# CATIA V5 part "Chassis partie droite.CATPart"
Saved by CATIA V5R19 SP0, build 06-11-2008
Part number: Bati.1
Bounding box of the stored display mesh (mm): x 0 to 60, y 0 to 700, z 0 to 900
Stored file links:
  C:\Users\Hicham57\Desktop\Chassis presse\Chassis partie droite.CATPart
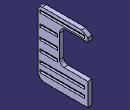
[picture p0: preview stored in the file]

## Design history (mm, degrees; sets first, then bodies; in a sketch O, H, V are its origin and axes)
Body1 (main body)
  Sketch1 on yz-plane, origin (0, 0, 0), H (0, 1, 0), V (0, 0, 1)
    line L1 (101.0295, 0) -> (700, 0)
    point P1 (700, 0)
    line L2 (700, 0) -> (700, 320)
    line L3 (700, 320) -> (365.2402, 320)
    line L4 (300, 385.2402) -> (300, 701.3231)
    line L5 (393.6769, 795) -> (700, 795)
    point P3 (700, 795)
    line L6 (700, 795) -> (700, 850)
    line L7 (700, 850) -> (613.3975, 900)
    line L8 (613.3975, 900) -> (58.246, 900)
    point P6 (0, 900)
    line L9 (0, 841.754) -> (0, 101.0295)
    arc A1 centre (365.2402, 385.2402) radius 65.2402 from (365.2402, 320) to (300, 385.2402) cw
    arc A2 centre (393.6769, 701.3231) radius 93.6769 from (300, 701.3231) to (393.6769, 795) cw
    arc A3 centre (58.246, 841.754) radius 58.246 from (58.246, 900) to (0, 841.754) ccw
    arc A4 centre (101.0295, 101.0295) radius 101.0295 from (101.0295, 0) to (0, 101.0295) cw
    length L2 = 320
    distance L3 L5 = 475
    distance L4 L9 = 300
    length L7 = 100
    angle L5 L7 = 150
    radius A1 = 65.2402
    radius A2 = 93.6769
    distance P6 O = 900
    radius A3 = 58.246
    distance O P1 = 700
    radius A4 = 101.0295
    horizontal: L1 H, L3 H, L5 H, L8 H
    vertical: L2 V, L4 V, L6 V, L9 V
    coincidence: P3 L2, P6 V, L8 P6, L9 P6, L1 O, L9 O
    tangency: A1 L3, A1 L4, A2 L4, A2 L5, A3 L8, A3 L9, A4 L1, A4 L9
  Pad1: profile Sketch1, direction (1, 0, 0), length 60
  Sketch2 on end face of Pad1, origin (60, 0, 0), H (0, 1, 0), V (0, 0, 1)
  Sketch3 on start face of Pad1, origin (0, 0, 0), H (0, -1, 0), V (0, 0, 1)
    line L1 (-655, 855) -> (-25, 855)
    line L2 (-25, 855) -> (-25, 815)
    line L3 (-25, 815) -> (-655, 815)
    line L4 (-655, 815) -> (-655, 855)
    line L5 (-275, 685) -> (-25, 685)
    line L6 (-25, 685) -> (-25, 645)
    line L7 (-25, 645) -> (-275, 645)
    line L8 (-275, 645) -> (-275, 685)
    point P7 (-25, 645)
    point P9 (-275, 525)
    line L9 (-275, 525) -> (-25, 525)
    line L10 (-25, 525) -> (-25, 485)
    line L11 (-25, 485) -> (-275, 485)
    line L12 (-275, 485) -> (-275, 525)
    point P11 (-25, 485)
    line L13 (-275, 380) -> (-25, 380)
    line L14 (-25, 380) -> (-25, 340)
    line L15 (-25, 340) -> (-275, 340)
    line L16 (-275, 340) -> (-275, 380)
    point P17 (-655, 240)
    line L17 (-655, 240) -> (-25, 240)
    line L18 (-25, 240) -> (-25, 200)
    line L19 (-25, 200) -> (-655, 200)
    line L20 (-655, 200) -> (-655, 240)
    point P19 (-25, 200)
    point P21 (-655, 130)
    line L21 (-655, 130) -> (-25, 130)
    line L22 (-25, 130) -> (-25, 90)
    line L23 (-25, 90) -> (-655, 90)
    line L24 (-655, 90) -> (-655, 130)
    point P23 (-25, 90)
    length L1 = 630
    length L2 = 40
    distance L3 H = 815
    length L8 = 40
    distance L11 L9 = 40
    distance L15 L13 = 40
    distance L6 L8 = 250
    length L15 = 250
    distance V L6 = 25
    distance L7 H = 645
    distance L11 H = 485
    distance L14 V = 25
    distance L15 H = 340
    distance L19 H = 200
    length L20 = 40
    length L24 = 40
    distance H L23 = 90
    horizontal: L1 H, L3 H, L5 H, L7 H, L9 H, L11 H, L13 H, L15 H, L17 H, L19 H, L21 H, L23 H
    vertical: L2 V, L4 V, L6 V, L8 V, L10 V, L12 V, L14 V, L16 V, L18 V, L20 V, L22 V, L24 V
    coincidence: P7 L2, P9 L8, P11 L2, P17 L4, P19 L14, P21 L4, P23 L2
  Pocket1: profile Sketch3, direction (1, 0, 0), length 25
  Sketch4 on end face of Pad1, origin (60, 0, 0), H (0, 1, 0), V (0, 0, 1)
    circle A1 centre (165, 835) radius 10
    point P1 (165, 835)
    circle A2 centre (565, 835) radius 10
    point P2 (565, 835)
    circle A3 centre (80, 665) radius 10
    point P3 (80, 665)
    circle A4 centre (220, 665) radius 10
    point P4 (220, 665)
    circle A5 centre (80, 505) radius 10
    point P5 (80, 505)
    circle A6 centre (220, 505) radius 10
    point P6 (220, 505)
    circle A7 centre (80, 360) radius 10
    point P7 (80, 360)
    circle A8 centre (220, 360) radius 10
    point P8 (220, 360)
    circle A9 centre (165, 220) radius 10
    point P9 (165, 220)
    circle A10 centre (365, 220) radius 10
    point P10 (365, 220)
    circle A11 centre (565, 220) radius 10
    point P11 (565, 220)
    circle A12 centre (165, 110) radius 10
    point P12 (165, 110)
    circle A13 centre (365, 110) radius 10
    point P13 (365, 110)
    circle A14 centre (565, 110) radius 10
    point P14 (565, 110)
    circle A15 centre (365, 835) radius 10
    point P15 (365, 835)
    reference projected line E1 (25, 815) -> (25, 855) from edge [end face of Pocket1 | face of Pocket1 from Sketch3.L2]
    reference projected line E2 (655, 815) -> (25, 815) from edge [end face of Pocket1 | face of Pocket1 from Sketch3.L3]
    reference projected line E3 (655, 815) -> (25, 815) from edge [end face of Pocket1 | face of Pocket1 from Sketch3.L3]
    reference projected line E4 (655, 815) -> (25, 815) from edge [end face of Pocket1 | face of Pocket1 from Sketch3.L3]
    reference projected line E5 (25, 200) -> (25, 240) from edge [start face of Pad1 | face of Pocket1 from Sketch3.L18]
    reference projected line E6 (655, 200) -> (25, 200) from edge [end face of Pocket1 | face of Pocket1 from Sketch3.L19]
    reference projected line E7 (655, 200) -> (25, 200) from edge [end face of Pocket1 | face of Pocket1 from Sketch3.L19]
    reference projected line E8 (655, 200) -> (25, 200) from edge [end face of Pocket1 | face of Pocket1 from Sketch3.L19]
    reference projected line E9 (25, 90) -> (25, 130) from edge [end face of Pocket1 | face of Pocket1 from Sketch3.L22]
    reference projected line E10 (655, 90) -> (25, 90) from edge [end face of Pocket1 | face of Pocket1 from Sketch3.L23]
    reference projected line E11 (655, 90) -> (25, 90) from edge [end face of Pocket1 | face of Pocket1 from Sketch3.L23]
    reference projected line E12 (655, 90) -> (25, 90) from edge [end face of Pocket1 | face of Pocket1 from Sketch3.L23]
    reference projected line E13 (25, 645) -> (25, 685) from edge [end face of Pocket1 | face of Pocket1 from Sketch3.L6]
    reference projected line E14 (275, 685) -> (275, 645) from edge [end face of Pocket1 | face of Pocket1 from Sketch3.L8]
    reference projected line E15 (275, 645) -> (25, 645) from edge [end face of Pocket1 | face of Pocket1 from Sketch3.L7]
    reference projected line E16 (25, 485) -> (25, 525) from edge [end face of Pocket1 | face of Pocket1 from Sketch3.L10]
    reference projected line E17 (275, 525) -> (275, 485) from edge [end face of Pocket1 | face of Pocket1 from Sketch3.L12]
    reference projected line E18 (275, 485) -> (25, 485) from edge [end face of Pocket1 | face of Pocket1 from Sketch3.L11]
    reference projected line E19 (25, 340) -> (25, 380) from edge [start face of Pad1 | face of Pocket1 from Sketch3.L14]
    reference projected line E20 (275, 380) -> (275, 340) from edge [end face of Pocket1 | face of Pocket1 from Sketch3.L16]
    reference projected line E21 (275, 340) -> (25, 340) from edge [end face of Pocket1 | face of Pocket1 from Sketch3.L15]
    radius A1 = 10
    radius A15 = 10
    radius A2 = 10
    radius A3 = 10
    radius A4 = 10
    radius A5 = 10
    radius A6 = 10
    radius A7 = 10
    radius A8 = 10
    radius A9 = 10
    radius A10 = 10
    radius A11 = 10
    radius A12 = 10
    radius A13 = 10
    radius A14 = 10
    distance A1 E1 = 150
    distance A1 E2 = 10
    distance A15 E3 = 10
    distance A2 E4 = 10
    distance P15 P1 = 200
    distance P2 P15 = 200
    distance P9 E5 = 140
    distance P9 P10 = 200
    distance P11 P10 = 200
    distance P9 E6 = 20
    distance P10 E7 = 20
    distance P11 E8 = 20
    distance P12 E9 = 140
    distance P12 P13 = 200
    distance P14 P13 = 200
    distance A12 E10 = 10
    distance A13 E11 = 10
    distance A14 E12 = 10
    distance P3 P4 = 140
    distance P3 E13 = 55
    distance P4 E14 = 55
    distance A3 E15 = 10
    distance E16 P5 = 55
    distance P5 P6 = 140
    distance P6 E17 = 55
    distance P6 E18 = 20
    distance P7 E19 = 55
    distance P8 P7 = 140
    distance E20 P8 = 55
    distance P8 E21 = 20
  Pocket2: profile Sketch4, direction (-1, 0, 0), length 60
  Sketch5 on end face of Pad1, origin (60, 0, 0), H (0, 1, 0), V (0, 0, 1)
    line L1 (25, 815) -> (655, 815)
    line L2 (655, 815) -> (655, 855)
    line L3 (655, 855) -> (25, 855)
    line L4 (25, 855) -> (25, 815)
    line L5 (25, 645) -> (275, 645)
    line L6 (275, 645) -> (275, 685)
    line L7 (275, 685) -> (25, 685)
    line L8 (25, 685) -> (25, 645)
    line L9 (25, 485) -> (275, 485)
    line L10 (275, 485) -> (275, 525)
    line L11 (275, 525) -> (25, 525)
    line L12 (25, 525) -> (25, 485)
    line L13 (25, 340) -> (275, 340)
    line L14 (275, 340) -> (275, 380)
    line L15 (275, 380) -> (25, 380)
    line L16 (25, 380) -> (25, 340)
    line L17 (25, 200) -> (655, 200)
    line L18 (655, 200) -> (655, 240)
    line L19 (655, 240) -> (25, 240)
    line L20 (25, 240) -> (25, 200)
    line L21 (25, 90) -> (655, 90)
    line L22 (655, 90) -> (655, 130)
    line L23 (655, 130) -> (25, 130)
    line L24 (25, 130) -> (25, 90)
    reference projected line E1 (655, 815) -> (25, 815) from edge [end face of Pocket1 | face of Pocket1 from Sketch3.L3]
    reference projected line E2 (25, 855) -> (655, 855) from edge [end face of Pocket1 | face of Pocket1 from Sketch3.L1]
    reference projected line E3 (655, 855) -> (655, 815) from edge [end face of Pocket1 | face of Pocket1 from Sketch3.L4]
    reference projected line E4 (25, 815) -> (25, 855) from edge [end face of Pocket1 | face of Pocket1 from Sketch3.L2]
    reference projected line E5 (275, 645) -> (25, 645) from edge [end face of Pocket1 | face of Pocket1 from Sketch3.L7]
    reference projected line E6 (25, 685) -> (275, 685) from edge [end face of Pocket1 | face of Pocket1 from Sketch3.L5]
    reference projected line E7 (25, 645) -> (25, 685) from edge [end face of Pocket1 | face of Pocket1 from Sketch3.L6]
    reference projected line E8 (275, 685) -> (275, 645) from edge [end face of Pocket1 | face of Pocket1 from Sketch3.L8]
    reference projected line E9 (25, 525) -> (275, 525) from edge [end face of Pocket1 | face of Pocket1 from Sketch3.L9]
    reference projected line E10 (275, 485) -> (25, 485) from edge [end face of Pocket1 | face of Pocket1 from Sketch3.L11]
    reference projected line E11 (275, 525) -> (275, 485) from edge [end face of Pocket1 | face of Pocket1 from Sketch3.L12]
    reference projected line E12 (25, 485) -> (25, 525) from edge [end face of Pocket1 | face of Pocket1 from Sketch3.L10]
    reference projected line E13 (25, 380) -> (275, 380) from edge [end face of Pocket1 | face of Pocket1 from Sketch3.L13]
    reference projected line E14 (275, 340) -> (25, 340) from edge [end face of Pocket1 | face of Pocket1 from Sketch3.L15]
    reference projected line E15 (275, 380) -> (275, 340) from edge [end face of Pocket1 | face of Pocket1 from Sketch3.L16]
    reference projected line E16 (25, 340) -> (25, 380) from edge [end face of Pocket1 | face of Pocket1 from Sketch3.L14]
    reference projected line E17 (25, 240) -> (655, 240) from edge [end face of Pocket1 | face of Pocket1 from Sketch3.L17]
    reference projected line E18 (655, 240) -> (655, 200) from edge [end face of Pocket1 | face of Pocket1 from Sketch3.L20]
    reference projected line E19 (655, 200) -> (25, 200) from edge [end face of Pocket1 | face of Pocket1 from Sketch3.L19]
    reference projected line E20 (25, 200) -> (25, 240) from edge [end face of Pocket1 | face of Pocket1 from Sketch3.L18]
    reference projected line E21 (25, 130) -> (655, 130) from edge [end face of Pocket1 | face of Pocket1 from Sketch3.L21]
    reference projected line E22 (655, 90) -> (25, 90) from edge [end face of Pocket1 | face of Pocket1 from Sketch3.L23]
    reference projected line E23 (655, 130) -> (655, 90) from edge [end face of Pocket1 | face of Pocket1 from Sketch3.L24]
    reference projected line E24 (25, 90) -> (25, 130) from edge [end face of Pocket1 | face of Pocket1 from Sketch3.L22]
    horizontal: L1 H, L3 H, L5 H, L7 H, L9 H, L11 H, L13 H, L15 H, L17 H, L19 H, L21 H, L23 H
    vertical: L2 V, L4 V, L6 V, L8 V, L10 V, L12 V, L14 V, L16 V, L18 V, L20 V, L22 V, L24 V
    coincidence: L1 E1, L3 E2, L2 E3, L4 E4, L5 E5, L7 E6, L8 E7, L6 E8, L11 E9, L9 E10, E11 L10, L12 E12, L15 E13, L13 E14, L14 E15, E16 L16, L19 E17, L18 E18, L17 E19, L20 E20, L23 E21, L21 E22, L22 E23, L24 E24
  Pocket3: profile Sketch5, direction (-1, 0, 0), length 30
  Sketch6 on start face of Pad1, origin (0, 0, 0), H (0, -1, 0), V (0, 0, 1)
    line L1 (-655, 855) -> (-25, 855)
    line L2 (-25, 855) -> (-25, 815)
    line L3 (-25, 815) -> (-655, 815)
    line L4 (-655, 815) -> (-655, 855)
    line L5 (-275, 685) -> (-25, 685)
    line L6 (-25, 685) -> (-25, 645)
    line L7 (-25, 645) -> (-275, 645)
    line L8 (-275, 645) -> (-275, 685)
    line L9 (-275, 525) -> (-25, 525)
    line L10 (-25, 525) -> (-25, 485)
    line L11 (-25, 485) -> (-275, 485)
    line L12 (-275, 485) -> (-275, 525)
    line L13 (-275, 380) -> (-25, 380)
    line L14 (-25, 380) -> (-25, 340)
    line L15 (-25, 340) -> (-275, 340)
    line L16 (-275, 340) -> (-275, 380)
    point P15 (-25, 340)
    line L17 (-655, 130) -> (-25, 130)
    line L18 (-25, 130) -> (-25, 90)
    line L19 (-25, 90) -> (-655, 90)
    line L20 (-655, 90) -> (-655, 130)
    reference projected line E1 (-25, 855) -> (-655, 855) from edge [start face of Pad1 | face of Pocket1 from Sketch3.L1]
    reference projected line E2 (-655, 815) -> (-25, 815) from edge [start face of Pad1 | face of Pocket1 from Sketch3.L3]
    reference projected line E3 (-25, 815) -> (-25, 855) from edge [start face of Pad1 | face of Pocket1 from Sketch3.L2]
    reference projected line E4 (-655, 855) -> (-655, 815) from edge [start face of Pad1 | face of Pocket1 from Sketch3.L4]
    reference projected line E5 (-25, 685) -> (-275, 685) from edge [start face of Pad1 | face of Pocket1 from Sketch3.L5]
    reference projected line E6 (-25, 645) -> (-25, 685) from edge [start face of Pad1 | face of Pocket1 from Sketch3.L6]
    reference projected line E7 (-275, 645) -> (-25, 645) from edge [start face of Pad1 | face of Pocket1 from Sketch3.L7]
    reference projected line E8 (-275, 685) -> (-275, 645) from edge [start face of Pad1 | face of Pocket1 from Sketch3.L8]
    reference projected line E9 (-25, 525) -> (-275, 525) from edge [start face of Pad1 | face of Pocket1 from Sketch3.L9]
    reference projected line E10 (-275, 485) -> (-25, 485) from edge [start face of Pad1 | face of Pocket1 from Sketch3.L11]
    reference projected line E11 (-275, 525) -> (-275, 485) from edge [start face of Pad1 | face of Pocket1 from Sketch3.L12]
    reference projected line E12 (-25, 485) -> (-25, 525) from edge [start face of Pad1 | face of Pocket1 from Sketch3.L10]
    reference projected line E13 (-25, 380) -> (-275, 380) from edge [start face of Pad1 | face of Pocket1 from Sketch3.L13]
    reference projected line E14 (-275, 340) -> (-25, 340) from edge [start face of Pad1 | face of Pocket1 from Sketch3.L15]
    reference projected line E15 (-275, 380) -> (-275, 340) from edge [start face of Pad1 | face of Pocket1 from Sketch3.L16]
    line L21 (-655, 240) -> (-25, 240)
    line L22 (-25, 240) -> (-25, 200)
    line L23 (-25, 200) -> (-655, 200)
    line L24 (-655, 200) -> (-655, 240)
    reference projected line E16 (-25, 200) -> (-25, 240) from edge [start face of Pad1 | face of Pocket1 from Sketch3.L18]
    reference projected line E17 (-655, 240) -> (-655, 200) from edge [start face of Pad1 | face of Pocket1 from Sketch3.L20]
    reference projected line E18 (-655, 200) -> (-25, 200) from edge [start face of Pad1 | face of Pocket1 from Sketch3.L19]
    reference projected line E19 (-25, 240) -> (-655, 240) from edge [start face of Pad1 | face of Pocket1 from Sketch3.L17]
    reference projected line E20 (-25, 90) -> (-25, 130) from edge [start face of Pad1 | face of Pocket1 from Sketch3.L22]
    reference projected line E21 (-25, 130) -> (-655, 130) from edge [start face of Pad1 | face of Pocket1 from Sketch3.L21]
    reference projected line E22 (-655, 90) -> (-25, 90) from edge [start face of Pad1 | face of Pocket1 from Sketch3.L23]
    reference projected line E23 (-655, 130) -> (-655, 90) from edge [start face of Pad1 | face of Pocket1 from Sketch3.L24]
    horizontal: L1 H, L3 H, L5 H, L7 H, L9 H, L11 H, L13 H, L15 H, L17 H, L19 H, L21 H, L23 H
    vertical: L2 V, L4 V, L6 V, L8 V, L10 V, L12 V, L14 V, L16 V, L18 V, L20 V, L22 V, L24 V
    coincidence: P15 L10, L1 E1, L3 E2, L2 E3, L4 E4, L5 E5, L6 E6, L7 E7, L8 E8, L9 E9, L11 E10, L12 E11, L10 E12, L13 E13, L15 E14, L16 E15, L22 E16, L24 E17, L23 E18, L21 E19, L18 E20, L17 E21, L19 E22, L20 E23
  Pad2: profile Sketch6, direction (1, 0, 0), length 25
  Sketch7 on end face of Pad1, origin (60, 0, 0), H (0, 1, 0), V (0, 0, 1)
    circle A1 centre (165, 835) radius 10
    circle A2 centre (365, 835) radius 10
    circle A3 centre (565, 835) radius 10
    circle A4 centre (80, 665) radius 10
    circle A5 centre (220, 665) radius 10
    circle A6 centre (80, 505) radius 10
    circle A7 centre (220, 505) radius 10
    circle A8 centre (80, 360) radius 10
    circle A9 centre (220, 360) radius 10
    circle A10 centre (165, 220) radius 10
    circle A11 centre (365, 220) radius 10
    circle A12 centre (565, 220) radius 10
    circle A13 centre (165, 110) radius 10
    circle A14 centre (365, 110) radius 10
    circle A15 centre (565, 110) radius 10
    reference projected circle E1 centre (165, 835) radius 10 from edge [end face of Pocket3 | face of Pocket2 from Sketch4.A1]
    reference projected circle E2 centre (365, 835) radius 10 from edge [end face of Pocket3 | face of Pocket2 from Sketch4.A15]
    reference projected circle E3 centre (565, 835) radius 10 from edge [end face of Pocket3 | face of Pocket2 from Sketch4.A2]
    reference projected circle E4 centre (80, 665) radius 10 from edge [end face of Pocket3 | face of Pocket2 from Sketch4.A3]
    reference projected circle E5 centre (220, 665) radius 10 from edge [end face of Pocket3 | face of Pocket2 from Sketch4.A4]
    reference projected circle E6 centre (80, 505) radius 10 from edge [end face of Pocket3 | face of Pocket2 from Sketch4.A5]
    reference projected circle E7 centre (220, 505) radius 10 from edge [end face of Pocket3 | face of Pocket2 from Sketch4.A6]
    reference projected circle E8 centre (80, 360) radius 10 from edge [end face of Pocket3 | face of Pocket2 from Sketch4.A7]
    reference projected circle E9 centre (220, 360) radius 10 from edge [end face of Pocket3 | face of Pocket2 from Sketch4.A8]
    reference projected circle E10 centre (165, 220) radius 10 from edge [end face of Pocket3 | face of Pocket2 from Sketch4.A9]
    reference projected circle E11 centre (365, 220) radius 10 from edge [end face of Pocket3 | face of Pocket2 from Sketch4.A10]
    reference projected circle E12 centre (565, 220) radius 10 from edge [end face of Pocket3 | face of Pocket2 from Sketch4.A11]
    reference projected circle E13 centre (565, 110) radius 10 from edge [end face of Pocket3 | face of Pocket2 from Sketch4.A14]
    reference projected circle E14 centre (365, 110) radius 10 from edge [end face of Pocket3 | face of Pocket2 from Sketch4.A13]
    reference projected circle E15 centre (165, 110) radius 10 from edge [end face of Pocket3 | face of Pocket2 from Sketch4.A12]
    coincidence: E1 A1, A2 E2, A3 E3, A4 E4, A5 E5, A6 E6, A7 E7, A8 E8, A9 E9, A10 E10, A11 E11, A12 E12, E13 A15, E14 A14, A13 E15
  Pocket4: profile Sketch7, direction (-1, 0, 0), length 100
